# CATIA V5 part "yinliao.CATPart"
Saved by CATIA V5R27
Part number: 饮料瓶
Material "Amber Mirror": density 2190 kg/m3, Young's modulus 6.5e+10 Pa, Poisson ratio 0.161, thermal expansion 8e-05 1/K
Bounding box of the stored display mesh (mm): x -26 to 26, y -25.976 to 25.977, z 0 to 110
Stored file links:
  G:\3D工程制图\180132104于洋\yinliaoping.CATPart
  E:\Program Files\Dassault Systemes\B27\win_b64\startup\materials\Catalog.CATMaterial
  E:\Program Files\Dassault Systemes\B27\win_b64\startup\materials\brushed_metal1.jpg
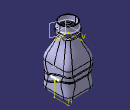
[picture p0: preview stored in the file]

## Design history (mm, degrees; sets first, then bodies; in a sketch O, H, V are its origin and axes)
Set1, material "Amber Mirror"
  Sketch1 on xy-plane, origin (0, 0, 0), H (1, 0, 0), V (0, 1, 0)
    line L1 (25, 25) -> (25, -25)
    line L2 (25, -25) -> (-25, -25)
    line L3 (-25, -25) -> (-25, 25)
    line L4 (-25, 25) -> (25, 25)
    length L1 = 50
    length L4 = 50
    vertical: L1 V, L3 V
    horizontal: L2 H, L4 H
    equidistance: L1 L3 O, L2 L4 O
  Sketch2 on face of Pad1 from Sketch1.L3, origin (-25, 0, 0), H (0, -1, 0), V (0, 0, 1)
    spline S1 through (-40, 20) (-10, 30) (10, 20) (40, 30)
  Extrude1: Element1 Sketch2, Lim1 60, Lim2 60
  MultiSel1: CommonCtxFeats ({extract ExtractElem face of Pad1 from Sketch1.L3}; {extract ExtractElem face of Fillet1}; {extract ExtractElem face of Pad1 from Sketch1.L2}; {extract ExtractElem face of Fillet1}; {extract ExtractElem face of Pad1 from Sketch1.L1}; {extract ExtractElem face of Fillet1}; {extract ExtractElem face of Pad1 from Sketch1.L4}; {extract ExtractElem face of Fillet1})
  Join1: Elements ({intersect ToIntersect1 {extract ExtractElem face of Pad1 from Sketch1.L1}, ToIntersect2 Extrude1}; {intersect ToIntersect1 {extract ExtractElem face of Fillet1}, ToIntersect2 Extrude1}; {intersect ToIntersect1 {extract ExtractElem face of Pad1 from Sketch1.L4}, ToIntersect2 Extrude1}; {intersect ToIntersect1 {extract ExtractElem face of Fillet1}, ToIntersect2 Extrude1}; {intersect ToIntersect1 {extract ExtractElem face of Pad1 from Sketch1.L3}, ToIntersect2 Extrude1}; {intersect ToIntersect1 {extract ExtractElem face of Fillet1}, ToIntersect2 Extrude1}; {intersect ToIntersect1 {extract ExtractElem face of Pad1 from Sketch1.L2}, ToIntersect2 Extrude1}; {intersect ToIntersect1 {extract ExtractElem face of Fillet1}, ToIntersect2 Extrude1})
  Sketch3 on face of Pad1 from Sketch1.L1, origin (25, 0, 0), H (0, 1, 0), V (0, 0, 1)
    spline S1 through (-40, 40) (-20, 30) (10, 40) (40, 30)
  Extrude2: Element1 Sketch3, Lim1 60, Lim2 60
  MultiSel2: CommonCtxFeats ({extract ExtractElem face of Pad1 from Sketch1.L1}; {extract ExtractElem face of Fillet1}; {extract ExtractElem face of Pad1 from Sketch1.L4}; {extract ExtractElem face of Fillet1}; {extract ExtractElem face of Pad1 from Sketch1.L3}; {extract ExtractElem face of Fillet1}; {extract ExtractElem face of Pad1 from Sketch1.L2}; {extract ExtractElem face of Fillet1})
  Plane1: type Normal, Curve Join1, RefPoint vertex [face of MultiSel1 | face of MultiSel1]
  Circle1: type CtrRad, Start 0, End 180, Center vertex [face of MultiSel1 | face of MultiSel1], Support Plane1, Radius 1, FirstDirection (-1, 0, 0)
  Plane2: type Normal, Curve {intersect ToIntersect1 {extract ExtractElem face of Pad1 from Sketch1.L1}, ToIntersect2 Extrude2}, RefPoint vertex of MultiSel2
Body1 (main body), material "无"
  Pad1: profile Sketch1, direction (0, 0, 1), length 50
  Fillet1: on edge [face of Pad1 from Sketch1.L4 | face of Pad1 from Sketch1.L1]; edge [face of Pad1 from Sketch1.L1 | face of Pad1 from Sketch1.L2]; edge [face of Pad1 from Sketch1.L3 | face of Pad1 from Sketch1.L4]; edge [face of Pad1 from Sketch1.L2 | face of Pad1 from Sketch1.L3]
  Fillet2: on edge [start face of Pad1 | face of Pad1 from Sketch1.L4]
  Plane3: type Offset, RefPlane end face of Pad1, Offset 40, reversed
  Sketch4 on Plane3, origin (0, 0, 90), H (1, 0, 0), V (0, -1, 0)
    circle A1 centre (0, 0) radius 15
  Pad2: profile Sketch4, direction (0, 0, 1), length 20
  Sketch5 on end face of Pad1, origin (0, 0, 50), H (1, 0, 0), V (0, 1, 0)
    point P1 (25, 0)
    distance P1 O = 25
    coincidence: P1 H
  Sketch6 on start face of Pad2, origin (0, 0, 90), H (1, 0, 0), V (0, -1, 0)
    point P1 (15, 0)
    distance P1 O = 15
    coincidence: P1 H
  Loft1: solid, Sections ({boundary Boundary {extract ExtractElem end face of Pad1}}; {boundary Boundary {extract ExtractElem start face of Pad2}}), StartFace end face of Pad1, EndFace start face of Pad2
  Slot1: profile Circle1, centre curve Join1
  Circle2: type CtrRad, Start 0, End 180, Center vertex of MultiSel2, Support Plane2, Radius 1, FirstDirection (1, 0, 0)
  Join2: Elements ({intersect ToIntersect1 {extract ExtractElem face of Pad1 from Sketch1.L1}, ToIntersect2 Extrude2}; {intersect ToIntersect1 {extract ExtractElem face of Fillet1}, ToIntersect2 Extrude2}; {intersect ToIntersect1 {extract ExtractElem face of Pad1 from Sketch1.L4}, ToIntersect2 Extrude2}; {intersect ToIntersect1 {extract ExtractElem face of Fillet1}, ToIntersect2 Extrude2}; {intersect ToIntersect1 {extract ExtractElem face of Pad1 from Sketch1.L3}, ToIntersect2 Extrude2}; {intersect ToIntersect1 {extract ExtractElem face of Fillet1}, ToIntersect2 Extrude2}; {intersect ToIntersect1 {extract ExtractElem face of Pad1 from Sketch1.L2}, ToIntersect2 Extrude2}; {intersect ToIntersect1 {extract ExtractElem face of Fillet1}, ToIntersect2 Extrude2})
  Rib1: profile Circle2, centre curve Join2
  Shell1: ExtOffset 0, Face end face of Pad2, IntOffset 1
  Plane4: type Offset, RefPlane start face of Pad1, Offset 91
  Sketch7 on Plane4, origin (0, 0, 91), H (1, 0, 0), V (0, 1, 0)
  Sketch8 on Plane4, origin (0, 0, 91), H (1, 0, 0), V (0, 1, 0)
    point P1 (15, 0)
    distance P1 O = 15
    coincidence: P1 H
  Helix1: Direction Z axis, RefPoint Sketch8, Pitch 2, Height 10, TaperAngle 0
  Point1: type OnCurve, Support Helix1, RefPoint vertex of Helix1, Length -6
  Line1: type PtDir, RefPoint vertex of Helix1, Direction (1, 0, 0), Start 0, End 10
  Connect1: Curve1 Line1, Point1 vertex of Line1, Tension1 1, Curve2 Helix1, Point2 Point1, Tension2 1
  Point2: type OnCurve, Support Connect1, RefPoint Sketch8, Length -6
  Line2: type PtDir, RefPoint Sketch8, Direction (1, 0, 0), Start 0, End 10
  Connect2: Curve1 Line2, Point1 vertex of Line2, Tension1 1, Curve2 Connect1, Point2 Point2, Tension2 1
Body2
  Sketch9 on face of Pad1 from Sketch1.L1, origin (25, 0, 0), H (0, 1, 0), V (0, 0, 1)
    polyline C1
    polyline C2
    polyline C3
    polyline C4
    polyline C5
    polyline C6
    polyline C7
    polyline C8
    polyline C9
    polyline C10
    polyline C11
    polyline C12
  Plane5: type Normal, Curve Connect2, RefPoint Point1
  Circle3: type CtrRad, Start 0, End 180, Center Point1, Support Plane5, Radius 2, FirstDirection (-0.9211, 0.3893, 0)
  Rib2: profile Circle3, centre curve Connect2
  Sketch10 on face of Pad1 from Sketch1.L1, origin (25, 0, 0), H (0, 1, 0), V (0, 0, 1)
